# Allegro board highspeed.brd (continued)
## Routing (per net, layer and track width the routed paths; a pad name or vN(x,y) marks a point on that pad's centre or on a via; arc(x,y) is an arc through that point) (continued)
A<0>: length 29.1
  TOP w0.127: U15.47 v1(19.05,91.13)
  BOTTOM w0.127: v1(19.05,91.13) 17.87,89.95 12.14,89.95 10.99,88.81 10.99,72.82 J3.54
A<1>: length 23.9
  TOP w0.127: v1(16.31,87.5) 19.29,87.5 19.68,87.9 U15.46
  BOTTOM w0.127: v1(16.31,87.5) 12.34,87.5 11.32,86.49 11.32,75.04 J3.55
A<2>: length 16.8
  TOP w0.127: U15.44 20.95,87.83 v1(21.11,87.68)
  BOTTOM w0.127: v1(21.11,87.68) 21.11,84.61 J3.56
A<3>: length 22.3
  TOP w0.127: v1(21.46,91.87) 21.46,91.02 21.59,90.89 U15.43
  BOTTOM w0.127: v1(21.46,91.87) 21.46,90.5 16.16,85.2 12.54,85.2 11.65,84.31 11.65,79.79 J3.57
A<4>: length 32.6
  TOP w0.127: v1(22.94,91.87) 22.94,90.97 22.86,90.89 U15.41
  BOTTOM w0.127: J3.58 14.08,79.9 14.08,78.59 13.06,77.58 12.54,77.58 11.65,76.69 11.65,75.66 12.16,75.15 13.34,75.15 21.79,83.6 21.79,89.41 22.94,90.55 v1(22.94,91.87)
A<5>: length 14.8
  TOP w0.127: U15.40 23.5,87.89 22.72,87.11 20.27,87.11 20.27,87.38 v1(20.27,87.38)
  BOTTOM w0.127: v1(20.27,87.38) 20.27,87.38 20.27,86.61 17.48,83.82 J3.59
A<6>: length 14.6
  TOP w0.127: v1(15.65,86.36) 23.97,86.36 24.77,87.15 U15.38
  BOTTOM w0.127: J3.60 v1(15.65,86.36)
A<7>: length 16
  TOP w0.127: J3.61 14,88.9 15.97,86.93 18.19,86.93 18.34,86.78 23.59,86.78 v1(23.95,87.15) ; U15.37 v1(25.4,87.15)
  BOTTOM w0.127: v1(25.4,87.15) 25.4,87.14 23.96,87.14 v1(23.95,87.15)
A<8>: length 31
  TOP w0.127: U14.36 v1(26.04,61.65) ; v1(23.16,49.63) 23.16,49.64 9,49.64 J3.13
  BOTTOM w0.127: v1(23.16,49.63) 26.04,52.5 v1(26.04,61.65)
A<9>: length 31
  TOP w0.127: J3.14 10.63,53.81 10.63,61.07 11.9,62.34 13.54,62.34 v1(15.29,64.08) ; U14.35 v1(26.67,65.1)
  BOTTOM w0.127: v1(26.67,65.1) 25.65,64.08 v1(15.29,64.08)
A<10>: length 31.2
  TOP w0.127: v1(15.67,65.68) 14.97,64.98 12.65,64.98 9.98,62.31 9.98,55.7 J3.15 ; v1(27.81,65.1) 27.81,64.52 27.94,64.39 U14.33
  BOTTOM w0.127: v1(27.81,65.1) 27.23,65.68 v1(15.67,65.68)
A<11>: length 28.3
  TOP w0.127: U14.32 28.57,61.67 27.3,60.4 26.62,60.4 v1(26.62,60.4)
  BOTTOM w0.127: v1(26.62,60.4) 26.62,61.91 25.98,62.54 17.38,62.54 14.46,59.62 14.46,58.63 13.06,57.24 8.98,57.24 J3.16
A<12>: length 31.5
  TOP w0.127: J3.17 9.32,60.12 9.32,64.12 12.25,67.04 15.19,67.04 16.58,65.64 16.58,64.98 v1(16.59,64.97) ; v1(19.02,65.1) 19.59,65.67 29.05,65.67 29.84,64.88 U14.30
  BOTTOM w0.127: v1(19.02,65.1) 18.9,64.97 16.59,64.97 v1(16.59,64.97)
A<13>: length 27.1
  TOP w0.127: v1(21.16,66.27) 29.08,66.27 30.48,64.87 U14.29
  BOTTOM w0.127: v1(21.16,66.27) 14.38,66.27 13.14,65.03 11.69,65.03 J3.18
A<14>: length 28.1
  TOP w0.127: v1(24.36,66.85) 29.84,66.85 31.75,64.95 U14.27
  BOTTOM w0.127: J3.19 8.76,63.5 9.65,64.39 9.65,64.5 12.19,67.04 24.17,67.04 v1(24.36,66.85)
A<15>: length 28.9
  TOP w0.127: J3.20 8.95,67.37 13.82,67.37 v1(14.66,68.2) ; U14.26 32.39,64.95 29.72,67.61 21.49,67.61 v1(21.49,67.61)
  BOTTOM w0.127: v1(21.49,67.61) 21.49,67.62 21.49,68.2 v1(14.66,68.2)
A<16>: length 38.8
  TOP w0.127: v1(16.46,38.68) 16.46,31.7 J3.37 ; U14.47 v1(19.05,61.6)
  BOTTOM w0.127: v1(16.46,38.69) 16.46,60.2 17.86,61.6 v1(19.05,61.6)
A<17>: length 39.6
  TOP w0.127: v1(14.63,37.52) 14.63,37.51 14.63,35.99 13.04,34.4 12.46,34.4 11.32,33.26 11.32,31.86 J3.38 ; U14.46 v1(19.68,60.43)
  BOTTOM w0.127: v1(19.68,60.43) 19.68,60.42 17.75,60.42 17.36,60.03 17.36,38.15 16.72,37.52 v1(14.63,37.52)
A<18>: length 74.1
  TOP w0.127: v1(18.01,59.84) 18.01,59.84 19.94,59.84 20.95,60.86 U14.44 ; J3.39 15.53,35.85 15.53,39.58 v1(18.01,42.06) 31.37,42.06 43.47,54.16 49.72,54.16 U17.6
  BOTTOM w0.127: v1(18.01,59.84) v1(18.01,42.06)
A<19>: length 66.5
  TOP w0.127: 48.89,55.88 48.89,57.66 48.64,57.91 19.26,57.91 v1(18.58,57.23) ; U14.43 v1(21.59,60.43)
  BOTTOM w0.127: v1(21.59,60.43) 20.7,59.54 20.23,59.54 18.58,57.89 v1(18.58,57.23) 18.58,41.37 17.68,40.48 17.68,36.7 16.54,35.56 J3.40
A<20>: length 75.9
  TOP w0.127: J3.41 17.56,42.96 31.74,42.96 43.27,54.49 44.96,54.49 46.36,55.88 ; U14.41 v1(22.86,60.98)
  BOTTOM w0.127: v1(22.86,60.98) 22.85,61 17.79,61 17.03,60.23 17.03,38.35 16.77,38.1 J3.41
A<21>: length 61.1
  TOP w0.127: J3.42 15.81,43.75 17.31,43.75 ; 43.81,55.88 31.36,43.42 17.64,43.42 17.31,43.75 ; U14.40 v1(23.5,61.65) ; v1(19.74,44.09) 17.66,44.09 17.31,43.75
  BOTTOM w0.127: v1(19.74,44.09) 19.74,56.68 23.5,60.44 v1(23.5,61.65)
A<22>: length 60.7
  TOP w0.127: U14.38 v1(24.77,61.65) ; 41.28,55.88 31.93,46.53 v1(15.37,46.53)
  BOTTOM w0.127: v1(24.77,61.65) 24.2,62.22 17.59,62.22 15.31,59.93 15.31,47.16 15.37,47.1 v1(15.37,46.53) 15.37,44.77 13.78,43.18 J3.43
A<23>: length 48.3
  TOP w0.127: J3.44 14.1,47.12 v1(20.95,47.12) 29.97,47.12 U17.1 ; U14.37 v1(25.4,61.06)
  BOTTOM w0.127: v1(20.95,47.12) 20.95,50.12 25.4,54.56 v1(25.4,61.06)
AEN: length 46.9
  TOP w0.127: U17.8 54.16,58.24 18.74,58.24 17.59,57.1 17.59,56.9 14.04,53.34 J3.47
BA<0>: length 133.7
  TOP w0.127: U16.2 v1(19.05,25.93) ; v1(61.29,92.94) 61.29,92.94 61.29,92.33 61.54,92.07 U7.6 ; U15.13 26.04,77.94 27.05,76.93 32.93,76.93 v1(33,76.99) ; U16.13 v1(26.04,26.77)
  BOTTOM w0.127: 26.04,26.15 v1(26.04,26.77) ; 26.04,26.15 25.82,25.93 19.05,25.93 v1(19.05,25.93) ; 26.04,26.15 33.01,26.15 35.55,28.69 35.55,75.71 33.95,77.31 ; v1(61.29,92.94) 61.29,92.94 61.29,93.51 34.74,93.51 33.95,92.71 33.95,77.31 ; 33.95,77.31 33.95,76.99 v1(33,76.99)
BA<1>: length 122.8
  TOP w0.127: v1(66.29,95.2) 66.29,94.21 67.16,93.34 U7.7 ; U16.14 v1(26.67,30.3) ; U16.3 v1(19.68,30.3) ; U15.14 v1(26.67,78.23)
  BOTTOM w0.127: v1(26.67,30.3) 26.67,31.31 26.34,31.64 ; 29,78.56 28.67,78.23 v1(26.67,78.23) ; 29,78.56 29.42,78.13 29.42,64.88 32.14,62.16 32.14,37.94 32.95,37.13 32.95,35.33 31.3,33.68 28.38,33.68 26.34,31.64 ; 29,78.56 29,85.07 30.03,86.1 30.03,90.37 34.86,95.2 v1(66.29,95.2) ; v1(19.68,30.3) 21.02,31.64 26.34,31.64
BA<2>: length 122.4
  TOP w0.127: U15.16 27.94,82.04 28.96,83.06 v1(29.59,83.06) ; U16.5 v1(20.95,30.3) ; U16.16 v1(27.94,30.3) ; U7.8 v1(69.39,94.61)
  BOTTOM w0.127: v1(20.95,30.3) 21.85,29.41 27.04,29.41 v1(27.94,30.3) 30.99,33.35 31.56,33.35 33.59,35.38 33.59,62.91 29.75,66.75 29.75,79.66 29.33,80.08 29.33,82.17 29.59,82.44 v1(29.59,83.06) 30.49,83.95 30.49,90.3 34.8,94.61 v1(69.39,94.61)
BA<3>: length 129.2
  TOP w0.127: v1(21.59,26.85) U16.6 21.59,30.68 22.38,31.47 31.75,31.47 v1(31.75,31.47) ; v1(30.48,82.47) 29.46,82.47 28.57,81.58 U15.17 ; U16.17 v1(28.57,26.85) ; U7.9 66.14,95.88 65.51,95.25 65.51,93.83 v1(65.51,93.83)
  BOTTOM w0.127: v1(21.59,26.85) 22.08,27.34 28.08,27.34 v1(28.57,26.85) ; v1(65.51,93.83) 65.5,93.83 34.61,93.83 31.68,90.91 31.68,83.68 v1(30.48,82.47) 30.48,70.76 34.24,66.99 34.24,33.7 32.34,31.8 31.76,31.8 31.76,31.48 v1(31.75,31.47)
BA<4>: length 75.3
  TOP w0.127: U16.19 v1(29.84,26.85) ; U15.19 29.84,81.69 v1(29.9,81.74) ; U16.8 v1(22.86,26.77)
  BOTTOM w0.127: v1(29.9,81.74) 30.08,81.55 30.08,69.85 33.92,66.01 33.92,34.6 29.84,30.53 29.84,27.67 ; 29.84,27.67 v1(29.84,26.85) ; 29.84,27.67 21.53,27.67 21.02,27.16 21.02,26.53 21.27,26.28 22.37,26.28 v1(22.86,26.77)
BA<5>: length 73.2
  TOP w0.127: U15.20 30.48,77.49 v1(31.06,77.49) ; v1(33.73,30.89) 33.73,27.25 32.33,25.85 24.64,25.85 23.5,26.99 U16.9 ; U16.20 v1(30.48,30.3)
  BOTTOM w0.127: v1(31.06,77.49) 31.06,71.58 34.57,68.08 34.57,31.72 v1(33.73,30.89) 31.06,30.89 v1(30.48,30.3)
BA<6>: length 67.3
  TOP w0.127: v1(31.75,30.3) U16.22 31.75,26.57 31.35,26.18 25.65,26.18 24.77,27.07 U16.11 ; U15.22 v1(31.75,78.28)
  BOTTOM w0.127: v1(31.75,30.3) 32.65,29.41 33.37,29.41 34.9,30.93 34.9,69.2 31.75,72.34 v1(31.75,78.28)
BA<7>: length 71.8
  TOP w0.127: U15.23 v1(32.39,81.74) ; U16.12 25.4,30.08 26.19,30.87 31.99,30.87 32.39,30.47 U16.23 v1(32.39,26.72)
  BOTTOM w0.127: v1(32.39,26.72) 35.22,29.56 35.22,70.18 32.39,73.02 v1(32.39,81.74)
BD<0>: length 44.4
  TOP w0.127: U15.12 25.4,81.81 26.04,82.45 v1(26.7,82.45) ; v1(51.9,96.88) 51.37,97.41 51.37,97.45 51.17,97.65 51.17,97.89 51.04,98.03 50.75,98.03 49.53,99.25 U7.25
  BOTTOM w0.127: v1(51.9,96.88) 51.77,96.75 31.95,96.75 26.7,91.49 v1(26.7,82.45)
BD<1>: length 56.3
  TOP w0.127: U7.24 50.8,98.73 51.5,98.03 51.5,97.78 51.83,97.45 52.14,97.45 52.47,97.12 52.47,96.64 52.14,96.31 51.66,96.31 51.33,96.64 51.33,96.99 50.86,97.46 v1(50,97.46) ; v1(33.58,97.46) 33.59,97.45 33.59,76.74 33.19,76.34 26.92,76.34 24.77,78.5 U15.11
  BOTTOM w0.127: v1(50,97.46) v1(33.58,97.46)
BD<2>: length 43.6
  TOP w0.127: U15.9 23.5,81.8 24.26,82.56 v1(24.26,83.24) ; U7.23 v1(52.07,98.02)
  BOTTOM w0.127: v1(24.26,83.24) 26.35,85.33 26.35,91.99 32.39,98.03 52.06,98.03 v1(52.07,98.02)
BD<3>: length 49.6
  TOP w0.127: U15.8 v1(22.86,77.57) ; U7.22 v1(53.34,95.78)
  BOTTOM w0.127: v1(22.86,77.57) 24.09,78.8 25.18,78.8 28.48,82.1 28.48,90.01 34.25,95.78 v1(53.34,95.78)
BD<4>: length 52.2
  TOP w0.127: U15.6 v1(21.59,82.09) ; U7.21 v1(54.61,102.64)
  BOTTOM w0.127: v1(21.59,82.09) 22.12,82.62 22.12,88.14 23.83,89.86 23.83,91.95 24.65,92.77 24.65,95.67 31.63,102.65 54.6,102.65 v1(54.61,102.64)
BD<5>: length 49.5
  TOP w0.127: U7.20 v1(55.88,98.58) ; U15.5 20.95,82.32 21.84,83.21 23.19,83.21 v1(23.19,83.21)
  BOTTOM w0.127: v1(55.88,98.58) 55.87,98.59 31.98,98.59 27.41,94.02 27.41,93.73 25.97,92.29 25.97,85.99 v1(23.19,83.21)
BD<6>: length 52.1
  TOP w0.127: U7.19 v1(57.15,97.18) ; v1(27.58,83.8) 27.57,83.8 21.97,83.8 19.68,81.52 U15.3
  BOTTOM w0.127: v1(57.15,97.18) 57.14,97.19 53.02,97.19 52.14,96.31 51.65,96.31 51.52,96.18 33.93,96.18 27.58,89.84 v1(27.58,83.8)
BD<7>: length 68.2
  TOP w0.127: v1(34.75,92.69) 34.75,76.86 30.68,72.8 24.77,72.8 19.05,78.51 U15.2 ; U7.18 v1(58.42,92.94)
  BOTTOM w0.127: v1(58.42,92.94) 58.17,92.68 v1(34.75,92.68)
BD<8>: length 3.6
  TOP w0.127: U14.13 26.04,55.46 25.4,55.46 U14.12
BD<9>: length 4.9
  TOP w0.127: U14.14 26.67,52.49 24.77,52.49 U14.11
BD<10>: length 8.7
  TOP w0.127: U14.9 23.5,55.79 24.13,56.42 27.54,56.42 27.94,56.03 U14.16
BD<11>: length 9
  TOP w0.127: U14.17 28.57,52.42 28.32,52.16 23.11,52.16 22.86,52.42 U14.8
BD<12>: length 12.3
  TOP w0.127: U14.6 21.59,55.48 22.86,56.75 28.57,56.75 29.84,55.48 U14.19
BD<13>: length 13.9
  TOP w0.127: U14.5 20.95,55.55 22.48,57.08 28.96,57.08 30.48,55.55 U14.20
BD<14>: length 15.7
  TOP w0.127: U14.3 19.68,52.47 20.48,51.68 30.96,51.68 31.75,52.47 U14.22
BD<15>: length 17.4
  TOP w0.127: U14.23 32.39,52.37 31.37,51.35 20.07,51.35 19.05,52.37 U14.2
BNC2: length 20.1
  TOP w0.2: L1.2 127.71,24.77 C9.1
  TOP w1.5: J1.1 125.3,32.38 122.56,29.63 L1.2
BNC3: length 22.4
  TOP w0.2: C13.1 121.83,4.28
  TOP w0.5: 121.83,4.28 L4.2
  TOP w1.5: J2.1 124.1,11.68 121.79,9.37 L4.2
BR<0>: length 55.4
  TOP w0.127: U25.19 222.47,22.52 227.91,27.97 233.41,27.97 238.11,32.67 242.4,36.96 252.48,36.96
BR<1>: length 54.9
  TOP w0.127: U25.18 222.99,21.25 228.44,26.7 233.94,26.7 239.01,31.77 241.65,34.42 252.48,34.42
BR<2>: length 54.4
  TOP w0.127: J5.59 240.91,31.88 239.91,30.87 234.46,25.43 228.96,25.43 223.52,19.98 U25.17
BR<3>: length 53.9
  TOP w0.127: 252.48,29.34 252.22,29.08 239.91,29.08 234.99,24.16 229.49,24.16 224.05,18.71 U25.16
BR<4>: length 53.6
  TOP w0.127: U25.15 224.57,17.45 230.02,22.89 235.52,22.89 239.61,26.98 251.79,26.98 251.91,27.11 252.17,27.11 J5.61
BR<5>: length 54.1
  TOP w0.127: 252.48,24.26 250.95,25.78 240.2,25.78 236.05,21.62 230.55,21.62 225.1,16.18 203.01,16.18
BR<6>: length 53.8
  TOP w0.127: 252.48,21.72 250.4,21.72 248.54,23.58 239.8,23.58 236.57,20.35 231.07,20.35 225.63,14.91 U25.13
BR<7>: length 52.6
  TOP w0.127: 203.01,13.64 226.16,13.64 231.6,19.08 237.1,19.08 238.2,20.18 251.47,20.18 252.48,19.18
BRD: length 13
  TOP w0.127: U7.73 v1(64.77,69.49)
  BOTTOM w0.127: v1(64.77,69.49) 64.61,69.66 60.07,69.66 59.05,68.64 U17.16
BRESET: length 39.6
  TOP w0.127: U7.12 66.04,99.54 63.36,96.87 63.3,96.87 60.38,93.94 v1(60.38,69.09)
  BOTTOM w0.127: v1(60.38,69.09) 60.38,64.72 61.59,63.5
BWR: length 26.2
  TOP w0.127: U17.17 54.44,65.57 39.01,65.57 37.61,66.97 37.61,68.09 38.88,69.36 39.52,69.36 40.64,70.48 U7.54
CLK1_N: length 279.3
  TOP w0.2: U8.19 151.22,56.53 151.65,56.96 157.77,56.96 158.21,57.39 158.21,60.4 158.41,60.6 159.01,60.6 159.21,60.4 159.21,53.76 159.64,53.32 160.57,53.32 161.01,53.76 161.01,60.4 161.21,60.6 161.81,60.6 162.01,60.4 162.01,57.39 162.44,56.96 164.16,56.96 166.99,54.13 166.99,51.77 173.45,45.31 174.06,45.31 175.76,47.01 176.04,47.01 176.47,46.59 176.47,46.3 172.62,42.46 172.62,41.85 173.28,41.19 173.9,41.19 177.74,45.03 178.02,45.03 178.45,44.61 178.45,44.32 174.6,40.48 174.6,39.87 175.27,39.2 175.88,39.2 177.58,40.9 177.86,40.9 178.99,39.77 199.09,39.77 199.53,40.2 199.53,42.92 199.73,43.12 200.33,43.12 200.53,42.92 200.53,40.2 200.96,39.77 201.89,39.77 202.33,40.2 202.33,42.92 202.53,43.12 203.13,43.12 203.33,42.92 203.33,40.2 203.76,39.77 204.69,39.77 205.13,40.2 205.13,42.92 205.33,43.12 205.93,43.12 206.13,42.92 206.13,40.2 206.56,39.77 207.49,39.77 207.93,40.2 207.93,42.92 208.13,43.12 208.73,43.12 208.93,42.92 208.93,40.2 209.36,39.77 210.29,39.77 210.73,40.2 210.73,42.92 210.93,43.12 211.53,43.12 211.73,42.92 211.73,40.2 212.16,39.77 213.09,39.77 213.53,40.2 213.53,42.92 213.73,43.12 214.33,43.12 214.53,42.92 214.53,40.2 214.96,39.77 215.89,39.77 216.33,40.2 216.33,42.92 216.53,43.12 217.13,43.12 217.33,42.92 217.33,40.2 217.76,39.77 225.99,39.77 229.01,42.79 229.01,44.56 229.35,44.9 v1(229.35,45.43) ; J5.2 256.52,96.41 238.44,96.41 229.01,86.99 229.01,83.12 v1(229.35,82.78)
  BOTTOM w0.2: v1(229.35,82.78) 229.35,82.25 229.01,81.91 229.01,64.79 228.58,64.36 227.64,64.36 227.21,64.79 227.21,66.5 227.01,66.7 226.41,66.7 226.21,66.5 226.21,64.79 225.78,64.36 224.84,64.36 224.41,64.79 224.41,66.5 224.21,66.7 223.61,66.7 223.41,66.5 223.41,64.79 222.98,64.36 222.04,64.36 221.61,64.79 221.61,66.5 221.41,66.7 220.81,66.7 220.61,66.5 220.61,63.55 220.81,63.36 228.58,63.36 229.01,62.92 229.01,46.3 229.35,45.96 v1(229.35,45.43)
CLK1_P: length 279.3
  TOP w0.2: J5.1 256.45,96.81 238.27,96.81 228.6,87.15 228.6,83.11 v1(228.27,82.78) ; U8.20 151.22,57.8 151.65,57.36 157.61,57.36 157.81,57.56 157.81,60.56 158.24,61 159.17,61 159.61,60.56 159.61,53.92 159.81,53.72 160.41,53.72 160.61,53.92 160.61,60.56 161.04,61 161.97,61 162.41,60.56 162.41,57.56 162.61,57.36 164.33,57.36 167.39,54.3 167.39,51.94 173.62,45.71 173.9,45.71 175.59,47.41 176.21,47.41 176.87,46.75 176.87,46.14 173.02,42.29 173.02,42.01 173.45,41.59 173.73,41.59 177.58,45.43 178.19,45.43 178.85,44.77 178.85,44.16 175,40.31 175,40.03 175.43,39.6 175.71,39.6 177.41,41.3 178.02,41.3 179.16,40.17 198.93,40.17 199.13,40.37 199.13,43.08 199.56,43.52 200.49,43.52 200.93,43.08 200.93,40.37 201.13,40.17 201.73,40.17 201.93,40.37 201.93,43.08 202.36,43.52 203.29,43.52 203.73,43.08 203.73,40.37 203.93,40.17 204.53,40.17 204.73,40.37 204.73,43.08 205.16,43.52 206.09,43.52 206.53,43.08 206.53,40.37 206.73,40.17 207.33,40.17 207.53,40.37 207.53,43.08 207.96,43.52 208.89,43.52 209.33,43.08 209.33,40.37 209.53,40.17 210.13,40.17 210.33,40.37 210.33,43.08 210.76,43.52 211.69,43.52 212.13,43.08 212.13,40.37 212.33,40.17 212.93,40.17 213.13,40.37 213.13,43.08 213.56,43.52 214.49,43.52 214.93,43.08 214.93,40.37 215.13,40.17 215.73,40.17 215.93,40.37 215.93,43.08 216.36,43.52 217.29,43.52 217.73,43.08 217.73,40.37 217.93,40.17 225.82,40.17 228.61,42.96 228.61,44.56 228.27,44.9 v1(228.27,45.43)
  BOTTOM w0.2: v1(228.27,45.43) 228.27,45.96 228.61,46.3 228.61,62.76 228.41,62.96 220.64,62.96 220.21,63.39 220.21,66.66 220.64,67.1 221.58,67.1 222.01,66.66 222.01,64.95 222.21,64.75 222.81,64.75 223.01,64.95 223.01,66.66 223.44,67.1 224.38,67.1 224.81,66.66 224.81,64.95 225.01,64.75 225.61,64.75 225.81,64.95 225.81,66.66 226.24,67.1 227.18,67.1 227.61,66.66 227.61,64.95 227.81,64.75 228.41,64.75 228.61,64.95 228.61,81.91 228.27,82.25 v1(228.27,82.78)
CLK2_N: length 282.5
  TOP w0.2: J5.4 256.57,91.28 253.13,91.28 253.07,91.33 238.66,91.33 232.02,84.7 232.02,83.64 232,83.62 232,83.25 232.34,82.91 v1(232.34,82.38) ; v1(233.44,46.19) 233.44,45.66 233.1,45.32 233.1,43.68 226.65,37.23 213.52,37.23 213.32,37.03 213.32,36.02 212.88,35.59 211.95,35.59 211.52,36.02 211.52,38.67 211.32,38.87 210.72,38.87 210.52,38.67 210.52,36.02 210.08,35.59 209.15,35.59 208.72,36.02 208.72,38.67 208.52,38.87 207.92,38.87 207.72,38.67 207.72,36.02 207.28,35.59 206.35,35.59 205.92,36.02 205.92,38.67 205.72,38.87 205.12,38.87 204.92,38.67 204.92,36.02 204.48,35.59 203.55,35.59 203.12,36.02 203.12,38.67 202.92,38.87 202.32,38.87 202.12,38.67 202.12,36.02 201.68,35.59 200.75,35.59 200.32,36.02 200.32,38.67 200.12,38.87 199.52,38.87 199.32,38.67 199.32,36.02 198.88,35.59 197.95,35.59 197.52,36.02 197.52,38.67 197.32,38.87 196.72,38.87 196.52,38.67 196.52,36.02 196.08,35.59 195.15,35.59 194.72,36.02 194.72,38.67 194.52,38.87 193.92,38.87 193.72,38.67 193.72,36.02 193.28,35.59 192.35,35.59 191.92,36.02 191.92,38.67 191.72,38.87 191.12,38.87 190.92,38.67 190.92,36.02 190.48,35.59 189.55,35.59 189.12,36.02 189.12,38.67 188.92,38.87 188.32,38.87 188.12,38.67 188.12,36.02 187.68,35.59 186.75,35.59 186.32,36.02 186.32,38.67 186.12,38.87 185.52,38.87 185.32,38.67 185.32,36.02 184.88,35.59 183.95,35.59 183.52,36.02 183.52,38.67 183.32,38.87 182.72,38.87 182.52,38.67 182.52,36.02 182.08,35.59 181.15,35.59 180.72,36.02 180.72,37.03 180.52,37.23 171.49,37.23 169.27,39.45 168.99,39.45 167.44,37.91 166.83,37.91 166.17,38.57 166.17,39.18 169.7,42.71 169.7,42.99 169.28,43.42 168.99,43.42 165.46,39.89 164.85,39.89 164.19,40.55 164.19,41.16 167.72,44.69 167.72,44.98 167.3,45.4 167.01,45.4 163.48,41.87 162.87,41.87 162.21,42.53 162.21,43.14 165.74,46.67 165.74,46.96 165.31,47.38 165.03,47.38 161.5,43.85 160.89,43.85 160.23,44.51 160.23,45.12 163.76,48.66 163.76,48.94 163.33,49.36 163.05,49.36 159.52,45.83 158.91,45.83 158.25,46.49 158.25,47.11 161.78,50.64 161.78,50.92 161.35,51.34 161.07,51.34 159.53,49.8 158.92,49.8 158.22,50.5 154.3,54.42 151.65,54.42 151.22,53.98 U8.17
  BOTTOM w0.2: v1(232.34,82.38) 232.34,81.85 232,81.51 232,48.86 233.1,47.76 233.1,47.06 233.44,46.72 v1(233.44,46.19)
CLK2_P: length 282.7
  TOP w0.2: U8.18 151.22,55.26 151.65,54.82 154.46,54.82 158.38,50.9 158.38,50.9 159.08,50.2 159.36,50.2 160.91,51.74 161.52,51.74 162.18,51.08 162.18,50.47 158.65,46.94 158.65,46.66 159.07,46.23 159.35,46.23 162.89,49.76 163.5,49.76 164.16,49.1 164.16,48.49 160.63,44.96 160.63,44.68 161.06,44.25 161.34,44.25 164.87,47.78 165.48,47.78 166.14,47.12 166.14,46.51 162.61,42.98 162.61,42.7 163.04,42.27 163.32,42.27 166.85,45.8 167.46,45.8 168.12,45.14 168.12,44.53 164.59,41 164.59,40.72 165.02,40.29 165.3,40.29 168.83,43.82 169.44,43.82 170.1,43.16 170.1,42.55 166.57,39.02 166.57,38.73 167,38.31 167.28,38.31 168.82,39.85 169.44,39.85 171.66,37.63 180.68,37.63 181.12,37.2 181.12,36.19 181.32,35.99 181.92,35.99 182.12,36.19 182.12,38.84 182.55,39.27 183.48,39.27 183.92,38.84 183.92,36.19 184.12,35.99 184.72,35.99 184.92,36.19 184.92,38.84 185.35,39.27 186.28,39.27 186.72,38.84 186.72,36.19 186.92,35.99 187.52,35.99 187.72,36.19 187.72,38.84 188.15,39.27 189.08,39.27 189.52,38.84 189.52,36.19 189.72,35.99 190.32,35.99 190.52,36.19 190.52,38.84 190.95,39.27 191.88,39.27 192.32,38.84 192.32,36.19 192.52,35.99 193.12,35.99 193.32,36.19 193.32,38.84 193.75,39.27 194.68,39.27 195.12,38.84 195.12,36.19 195.32,35.99 195.92,35.99 196.12,36.19 196.12,38.84 196.55,39.27 197.48,39.27 197.92,38.84 197.92,36.19 198.12,35.99 198.72,35.99 198.92,36.19 198.92,38.84 199.35,39.27 200.28,39.27 200.72,38.84 200.72,36.19 200.92,35.99 201.52,35.99 201.72,36.19 201.72,38.84 202.15,39.27 203.08,39.27 203.52,38.84 203.52,36.19 203.72,35.99 204.32,35.99 204.52,36.19 204.52,38.84 204.95,39.27 205.88,39.27 206.32,38.84 206.32,36.19 206.52,35.99 207.12,35.99 207.32,36.19 207.32,38.84 207.75,39.27 208.68,39.27 209.12,38.84 209.12,36.19 209.32,35.99 209.92,35.99 210.12,36.19 210.12,38.84 210.55,39.27 211.48,39.27 211.92,38.84 211.92,36.19 212.12,35.99 212.72,35.99 212.92,36.19 212.92,37.2 213.35,37.63 226.48,37.63 232.7,43.85 232.7,45.32 232.36,45.66 v1(232.36,46.19) ; v1(231.26,82.38) 231.26,82.91 231.6,83.25 231.6,83.79 231.62,83.81 231.62,84.86 238.49,91.73 253.07,91.73 253.13,91.68 256.5,91.68 257.56,92.74 257.56,92.84
  BOTTOM w0.2: v1(232.36,46.19) 232.36,46.72 232.7,47.06 232.7,47.6 231.6,48.7 231.6,81.51 231.26,81.85 v1(231.26,82.38)
CLK3_N: length 276.4
  TOP w0.2: v1(237.54,43.78) 237.54,43.25 237.2,42.91 237.2,42.21 235.46,40.46 233.58,40.46 226.54,33.42 166.39,33.42 163.95,35.87 163.95,36.48 164.5,37.03 164.5,37.31 164.07,37.74 163.79,37.74 162.24,36.19 161.63,36.19 160.97,36.85 160.97,37.47 162.51,39.01 162.51,39.29 162.09,39.72 161.81,39.72 160.26,38.17 159.65,38.17 158.99,38.83 158.99,39.45 160.53,40.99 160.53,41.27 160.11,41.7 159.83,41.7 158.28,40.15 157.67,40.15 157.01,40.82 157.01,41.43 158.55,42.97 158.55,43.25 158.13,43.68 157.84,43.68 157.3,43.13 156.68,43.13 154.39,45.42 154.39,48.92 152.71,50.61 151.65,50.61 151.22,50.18 U8.14 ; v1(235.84,78.28) 235.84,78.81 235.5,79.15 235.5,82.38 239.38,86.25 242.03,86.25 242.47,86.69 242.47,89.13 242.67,89.33 243.27,89.33 243.47,89.13 243.47,83.62 243.9,83.18 244.83,83.18 245.27,83.62 245.27,89.13 245.47,89.33 246.07,89.33 246.27,89.13 246.27,83.62 246.7,83.18 247.63,83.18 248.07,83.62 248.07,89.13 248.27,89.33 248.87,89.33 249.07,89.13 249.07,86.69 249.5,86.25 256.52,86.25 J5.6
  BOTTOM w0.2: v1(235.84,78.28) 235.84,77.75 235.5,77.41 235.5,77.04 236.5,76.04 236.5,73.82 236.7,73.62 239,73.62 239.44,73.18 239.44,72.25 239,71.82 233.76,71.82 233.56,71.62 233.56,71.02 233.76,70.82 239,70.82 239.44,70.38 239.44,69.45 239,69.02 233.76,69.02 233.56,68.82 233.56,68.22 233.76,68.02 239,68.02 239.44,67.58 239.44,66.65 239,66.22 233.76,66.22 233.56,66.02 233.56,65.42 233.76,65.22 236.07,65.22 236.5,64.78 236.5,61.46 236.7,61.26 238.31,61.26 238.75,60.83 238.75,59.9 238.31,59.46 234.45,59.46 234.25,59.26 234.25,58.66 234.45,58.46 238.31,58.46 238.75,58.03 238.75,57.1 238.31,56.66 234.45,56.66 234.25,56.46 234.25,55.86 234.45,55.66 238.31,55.66 238.75,55.23 238.75,54.3 238.31,53.86 234.45,53.86 234.25,53.66 234.25,53.06 234.45,52.86 238.31,52.86 238.75,52.43 238.75,51.5 238.31,51.06 234.45,51.06 234.25,50.86 234.25,50.26 234.45,50.06 236.07,50.06 236.5,49.63 236.5,45.59 236.77,45.59 237.2,45.16 237.2,44.65 237.54,44.31 v1(237.54,43.78)
CLK3_P: length 276.4
  TOP w0.2: U8.15 151.22,51.45 151.65,51.01 152.87,51.01 154.79,49.09 154.79,45.59 156.85,43.53 157.13,43.53 157.68,44.08 158.29,44.08 158.95,43.42 158.95,42.81 157.41,41.26 157.41,40.98 157.83,40.55 158.11,40.55 159.66,42.1 160.27,42.1 160.93,41.44 160.93,40.83 159.39,39.28 159.39,39 159.82,38.57 160.1,38.57 161.64,40.12 162.25,40.12 162.91,39.46 162.91,38.84 161.37,37.3 161.37,37.02 161.8,36.59 162.08,36.59 163.62,38.14 164.24,38.14 164.9,37.48 164.9,36.86 164.35,36.31 164.35,36.03 166.56,33.82 226.37,33.82 233.42,40.86 235.29,40.86 236.8,42.37 236.8,42.91 236.46,43.25 v1(236.46,43.78) ; 257.56,87.76 256.45,86.66 249.67,86.66 249.47,86.85 249.47,89.29 249.03,89.73 248.1,89.73 247.67,89.29 247.67,83.78 247.47,83.58 246.87,83.58 246.67,83.78 246.67,89.29 246.23,89.73 245.3,89.73 244.87,89.29 244.87,83.78 244.67,83.58 244.07,83.58 243.87,83.78 243.87,89.29 243.44,89.73 242.5,89.73 242.07,89.29 242.07,86.85 241.87,86.66 239.21,86.66 235.1,82.55 235.1,79.15 234.76,78.81 v1(234.76,78.28)
  BOTTOM w0.2: v1(236.46,43.78) 236.46,44.31 236.8,44.65 236.8,44.99 236.6,45.19 236.3,45.19 236.1,45.39 236.1,49.46 235.9,49.66 234.28,49.66 233.85,50.1 233.85,51.03 234.28,51.46 238.15,51.46 238.35,51.66 238.35,52.26 238.15,52.46 234.28,52.46 233.85,52.9 233.85,53.83 234.28,54.26 238.15,54.26 238.35,54.46 238.35,55.06 238.15,55.26 234.28,55.26 233.85,55.7 233.85,56.63 234.28,57.06 238.15,57.06 238.35,57.26 238.35,57.86 238.15,58.06 234.28,58.06 233.85,58.5 233.85,59.43 234.28,59.86 238.15,59.86 238.35,60.06 238.35,60.66 238.15,60.86 236.53,60.86 236.1,61.3 236.1,64.62 235.9,64.82 233.6,64.82 233.16,65.25 233.16,66.18 233.6,66.62 238.84,66.62 239.04,66.82 239.04,67.42 238.84,67.62 233.6,67.62 233.16,68.05 233.16,68.98 233.6,69.42 238.84,69.42 239.04,69.62 239.04,70.22 238.84,70.42 233.6,70.42 233.16,70.85 233.16,71.78 233.6,72.22 238.84,72.22 239.04,72.42 239.04,73.02 238.84,73.22 236.53,73.22 236.1,73.65 236.1,75.87 235.1,76.87 235.1,77.41 234.76,77.75 v1(234.76,78.28)
CLK4_N: length 285.8
  TOP w0.2: v1(240.94,75.08) 240.94,75.61 240.6,75.95 240.6,80.01 241.77,81.19 256.5,81.19 J5.8 ; v1(239.19,42.03) 239.15,42.03 237.9,40.78 237.9,40.48 228.3,30.88 223.74,30.88 223.54,30.68 223.54,27.14 223.11,26.71 222.18,26.71 221.74,27.14 221.74,30.68 221.54,30.88 220.94,30.88 220.74,30.68 220.74,27.14 220.31,26.71 219.38,26.71 218.94,27.14 218.94,30.68 218.74,30.88 218.14,30.88 217.94,30.68 217.94,27.14 217.51,26.71 216.58,26.71 216.14,27.14 216.14,30.68 215.94,30.88 215.34,30.88 215.14,30.68 215.14,27.14 214.71,26.71 213.78,26.71 213.34,27.14 213.34,30.68 213.14,30.88 212.54,30.88 212.34,30.68 212.34,27.14 211.91,26.71 210.98,26.71 210.54,27.14 210.54,30.68 210.34,30.88 209.74,30.88 209.54,30.68 209.54,27.14 209.11,26.71 208.18,26.71 207.74,27.14 207.74,30.68 207.54,30.88 206.94,30.88 206.74,30.68 206.74,27.14 206.31,26.71 205.38,26.71 204.94,27.14 204.94,30.68 204.74,30.88 204.14,30.88 203.94,30.68 203.94,27.14 203.51,26.71 202.58,26.71 202.14,27.14 202.14,30.68 201.94,30.88 201.34,30.88 201.14,30.68 201.14,27.14 200.71,26.71 199.78,26.71 199.34,27.14 199.34,30.68 199.14,30.88 198.54,30.88 198.34,30.68 198.34,27.14 197.91,26.71 196.98,26.71 196.54,27.14 196.54,30.68 196.34,30.88 161,30.88 156.96,34.92 156.68,34.92 155.86,34.1 155.25,34.1 154.66,34.69 154.66,35.3 156.75,37.39 156.75,37.67 156.39,38.03 156.11,38.03 154.02,35.94 153.41,35.94 152.82,36.53 152.82,37.14 154.91,39.23 154.91,39.51 154.55,39.87 154.27,39.87 153.45,39.05 152.83,39.05 151.85,40.03 151.85,47.87 151.65,48.07 151.22,47.64 150.01,47.64
  BOTTOM w0.2: v1(240.94,75.08) 240.94,74.55 240.6,74.21 240.6,63.92 240.8,63.72 241.4,63.72 241.6,63.92 241.6,66.66 242.03,67.1 242.97,67.1 243.4,66.66 243.4,63.92 243.6,63.72 244.2,63.72 244.4,63.92 244.4,66.66 244.83,67.1 245.77,67.1 246.2,66.66 246.2,63.92 246.4,63.72 247,63.72 247.2,63.92 247.2,66.66 247.63,67.1 248.57,67.1 249,66.66 249,62.35 248.57,61.92 240.8,61.92 240.6,61.72 240.6,46.08 239.14,44.62 239.14,43.53 238.85,43.24 238.85,42.9 239.19,42.56 v1(239.19,42.03)
CLK4_P: length 285.5
  TOP w0.2: v1(239.86,75.08) 239.86,75.61 240.2,75.95 240.2,80.18 241.61,81.59 256.47,81.59 257.56,82.68 ; v1(238.11,42.03) 238.11,41.56 237.5,40.95 237.5,40.65 228.13,31.28 223.58,31.28 223.14,30.85 223.14,27.31 222.94,27.11 222.34,27.11 222.14,27.31 222.14,30.85 221.71,31.28 220.78,31.28 220.34,30.85 220.34,27.31 220.14,27.11 219.54,27.11 219.34,27.31 219.34,30.85 218.91,31.28 217.98,31.28 217.54,30.85 217.54,27.31 217.34,27.11 216.74,27.11 216.54,27.31 216.54,30.85 216.11,31.28 215.18,31.28 214.74,30.85 214.74,27.31 214.54,27.11 213.94,27.11 213.74,27.31 213.74,30.85 213.31,31.28 212.38,31.28 211.94,30.85 211.94,27.31 211.74,27.11 211.14,27.11 210.94,27.31 210.94,30.85 210.51,31.28 209.58,31.28 209.14,30.85 209.14,27.31 208.94,27.11 208.34,27.11 208.14,27.31 208.14,30.85 207.71,31.28 206.78,31.28 206.34,30.85 206.34,27.31 206.14,27.11 205.54,27.11 205.34,27.31 205.34,30.85 204.91,31.28 203.98,31.28 203.54,30.85 203.54,27.31 203.34,27.11 202.74,27.11 202.54,27.31 202.54,30.85 202.11,31.28 201.18,31.28 200.74,30.85 200.74,27.31 200.54,27.11 199.94,27.11 199.74,27.31 199.74,30.85 199.31,31.28 198.38,31.28 197.94,30.85 197.94,27.31 197.74,27.11 197.14,27.11 196.94,27.31 196.94,30.85 196.51,31.28 161.17,31.28 157.13,35.32 156.52,35.32 155.7,34.5 155.41,34.5 155.06,34.85 155.06,35.14 157.15,37.22 157.15,37.83 156.55,38.43 155.94,38.43 153.86,36.34 153.57,36.34 153.22,36.69 153.22,36.98 155.31,39.06 155.31,39.67 154.71,40.27 154.1,40.27 153.28,39.45 153,39.45 152.25,40.19 152.25,48.04 151.82,48.47 151.65,48.47 151.22,48.91 U8.13
  BOTTOM w0.2: v1(238.11,42.03) 238.11,42.56 238.45,42.9 238.45,43.41 238.74,43.69 238.74,44.78 240.2,46.25 240.2,61.89 240.63,62.32 248.4,62.32 248.6,62.52 248.6,66.5 248.4,66.7 247.8,66.7 247.6,66.5 247.6,63.75 247.17,63.32 246.23,63.32 245.8,63.75 245.8,66.5 245.6,66.7 245,66.7 244.8,66.5 244.8,63.75 244.37,63.32 243.43,63.32 243,63.75 243,66.5 242.8,66.7 242.2,66.7 242,66.5 242,63.75 241.57,63.32 240.63,63.32 240.2,63.75 240.2,74.21 239.86,74.55 v1(239.86,75.08)
CLOCK_IO: length 330.9
  TOP w0.127: 125.3,51.38 133.25,51.38 arc(133.65,51.22) 133.81,50.82 133.81,40.44 134.14,40.11 136.02,40.11 arc(136.58,40.67) 136.02,41.24 135.5,41.24 arc(134.94,41.8) 135.5,42.36 136.02,42.36 arc(136.58,42.93) 136.02,43.49 135.5,43.49 arc(134.94,44.05) 135.5,44.62 136.02,44.62 arc(136.58,45.18) 136.02,45.75 135.5,45.75 arc(134.94,46.31) 135.5,46.87 136.02,46.87 arc(136.58,47.44) 136.02,48 135.5,48 arc(134.94,48.56) 135.5,49.13 136.02,49.13 arc(136.58,49.69) 136.02,50.25 135.5,50.25 arc(134.94,50.82) 135.5,51.38 136.02,51.38 arc(136.58,51.94) 136.02,52.51 135.5,52.51 arc(134.94,53.07) 135.5,53.63 136.02,53.63 arc(136.58,54.2) 136.02,54.76 135.5,54.76 arc(134.94,55.33) 135.5,55.89 136.02,55.89 arc(136.58,56.45) 136.02,57.02 135.5,57.02 arc(134.94,57.58) 135.5,58.14 136.02,58.14 arc(136.58,58.71) 136.02,59.27 135.5,59.27 arc(134.94,59.83) 135.5,60.4 136.02,60.4 arc(136.58,60.96) 136.02,61.52 135.5,61.52 arc(134.94,62.09) 135.5,62.65 arc(135.8,62.77) 135.92,63.06 135.92,69.77 arc(136.33,70.18) 136.74,69.77 136.74,62.88 arc(136.81,62.72) 136.97,62.65 arc(137.13,62.58) 137.2,62.42 137.2,51.79 arc(137.32,51.5) 137.61,51.38 138.47,51.38 138.6,51.51 138.6,56.05 138.73,56.18 140.47,56.18 U8.2 ; 125.3,51.38 125.3,71.45 125.43,71.58 127.65,71.58 arc(127.94,71.46) 128.06,71.17 128.06,61.39 arc(128.47,60.98) 128.89,61.39 128.89,71.17 arc(129.3,71.58) 129.71,71.17 129.71,61.39 arc(130.13,60.98) 130.54,61.39 130.54,71.17 arc(130.96,71.58) 131.37,71.17 131.37,61.39 arc(131.78,60.98) 132.2,61.39 132.2,71.17 arc(132.32,71.46) 132.61,71.58 142.61,71.58 U24.11 ; 125.3,51.38 125.3,44.89 126.61,43.58 v1(131.2,43.58) ; v1(189.2,8.28) 198.92,8.28 U25.11
  TOP w0.802: R19.2 125.3,51.38
  BOTTOM w0.127: v1(189.2,8.28) 182.9,14.58 176.5,14.58 148.6,42.48 138.7,42.48 137.6,43.58 v1(131.2,43.58)
D<0>: length 92.4
  TOP w0.127: U16.26 v1(32.39,35.66) ; U16.37 v1(25.4,35.66) v1(25.4,34.37)
  BOTTOM w0.127: J3.28 4.61,83.35 4.61,31.97 7.15,29.43 15.91,29.43 18.78,32.3 23.33,32.3 v1(25.4,34.37) ; v1(25.4,35.66) v1(32.39,35.66)
D<1>: length 73.1
  TOP w0.127: v1(14.58,45.85) 23.14,45.85 v1(24.77,44.22) ; U16.38 v1(24.77,39.85) ; v1(24.77,41.17) 30.1,41.17 31.75,39.52 U16.27
  BOTTOM w0.127: v1(24.77,39.85) v1(24.77,41.17) v1(24.77,44.22) ; v1(14.58,45.85) 13.33,47.1 7.2,47.1 6.57,47.73 6.57,63.99 7.46,64.88 7.98,64.88 9,65.89 9,82.44 J3.27
D<2>: length 80.4
  TOP w0.127: U16.40 v1(23.5,39.7) ; U16.29 v1(30.48,39.7)
  BOTTOM w0.127: 23.5,39.13 20.89,36.53 20.89,35.07 20,34.18 6.86,34.18 5.59,35.45 5.59,70.59 7.49,72.5 8.04,72.5 8.67,73.13 8.67,80.23 J3.26 ; 23.5,39.13 v1(23.5,39.7) ; 23.5,39.13 29.91,39.13 v1(30.48,39.7)
D<3>: length 79.4
  TOP w0.127: U16.30 v1(29.84,34.95) ; U16.41 22.86,36.49 22.94,36.41 v1(22.94,34.95)
  BOTTOM w0.127: J3.25 4.93,76.05 4.93,33.67 6.97,31.64 15.71,31.64 17.02,32.95 20.94,32.95 v1(22.94,34.95) v1(29.84,34.95)
D<4>: length 74.3
  TOP w0.127: v1(21.51,36.25) 21.59,36.32 U16.43 ; U16.32 28.57,36.55 28.27,36.25 v1(28.12,36.25)
  BOTTOM w0.127: J3.24 5.26,73.84 5.26,33.87 7.17,31.97 14.24,31.97 15.88,33.6 19.99,33.6 21.51,35.13 v1(21.51,36.25) 22.41,37.14 27.86,37.14 28.12,36.89 v1(28.12,36.25)
D<5>: length 64.1
  TOP w0.127: U16.44 v1(20.95,39.7) ; J3.23 6.57,72.61 6.57,45.18 7.08,44.67 20.36,44.67 v1(20.95,45.26) ; U16.33 v1(27.94,39.7)
  BOTTOM w0.127: v1(27.94,39.7) 27.94,43.1 25.78,45.26 v1(20.95,45.26) v1(20.95,39.7)
D<6>: length 65
  TOP w0.127: U16.35 26.67,34.74 25.4,33.47 20.99,33.47 v1(19.68,34.77) U16.46
  BOTTOM w0.127: J3.22 5.91,69.41 5.91,35.65 7.06,34.51 18.85,34.51 19.12,34.77 v1(19.68,34.77)
D<7>: length 58.4
  TOP w0.127: U16.36 26.04,39.53 25.15,40.42 19.2,40.42 19.05,40.27 ; v1(17.04,36.93) 17.04,39.25 18.06,40.27 19.05,40.27 ; U16.47 19.05,40.27
  BOTTOM w0.127: v1(17.04,36.93) 7.26,36.93 6.24,37.95 6.24,67.2 J3.21
D<8>: length 96.1
  TOP w0.127: U15.36 26.04,91.35 24.89,92.49 7.13,92.49 1.54,86.9 1.54,26.54 2.68,25.4 J3.4
D<9>: length 89.7
  TOP w0.127: U15.35 26.67,91.29 25.15,92.82 14.88,92.82 v1(14.63,93.07)
  BOTTOM w0.127: J3.5 4.28,31.28 4.28,89.64 7.45,92.82 14.63,92.82 14.63,93.06 v1(14.63,93.07)
D<10>: length 83.7
  TOP w0.127: U15.33 27.94,87.82 25.91,85.79 15.35,85.79 13.41,87.74 7.02,87.74 4.61,85.32 4.61,33.49 J3.6
D<11>: length 80.9
  TOP w0.127: J3.7 5.26,35.38 5.26,85.51 7.17,87.41 13.22,87.41 15.17,85.46 26.16,85.46 28.57,87.88 U15.32
D<12>: length 76.9
  TOP w0.127: U15.30 29.84,86.73 28.19,85.08 7.37,85.08 5.59,83.3 5.59,37.59 J3.8
D<13>: length 71.8
  TOP w0.127: U15.29 30.48,86.77 28.45,84.74 18.21,84.74 13.59,80.12 7.5,80.12 5.91,78.53 5.91,39.8 J3.9
D<14>: length 68.4
  TOP w0.127: J3.10 6.24,42.02 6.24,76.44 7.38,77.58 13.03,77.58 19.81,84.36 28.7,84.36 31.75,87.41 U15.27
D<15>: length 111.1
  TOP w0.127: v1(24.08,95.61) 24.08,95.6 27.69,95.6 32.39,90.9 U15.26 ; J3.11 9,41.8 9,30.32 8.11,29.43 7.13,29.43 3.95,32.6 3.95,86.72 7.51,90.28 13.95,90.28 15.52,91.85 v1(19.63,91.85)
  BOTTOM w0.127: v1(19.63,91.85) 19.63,94.08 21.16,95.6 24.08,95.6 v1(24.08,95.61)
DATA: length 57.8
  TOP w0.127: U7.14 v1(63.5,101.78)
  BOTTOM w0.127: v1(63.5,101.78) 61.49,103.79 19.02,103.79 17.36,102.14 17.36,95.03 U18.1
DCLK: length 56.5
  TOP w0.127: U18.2 27.38,100.41 36.7,100.41 v1(36.7,100.41) ; U7.10 v1(70.33,97.16)
  BOTTOM w0.127: v1(36.7,100.41) 68.18,100.41 70.34,98.25 70.34,97.16 v1(70.33,97.16)
DDIR: length 81.5
  TOP w0.127: v1(48.31,57.33) 48.05,57.59 35.61,57.59 33.02,54.99 U14.24 33.02,52.42 31.62,51.03 19.68,51.03 18.41,52.29 ; U14.1 18.41,52.29 ; 18.41,52.29 12.16,52.29 11.65,52.8 11.65,61.5 12.16,62.01 14.43,62.01 17.48,65.06 17.48,75.27 18.41,76.21 U15.1
  BOTTOM w0.127: v1(48.31,57.33) 48.61,57.33 48.89,57.33 48.89,63.5
DEN: length 72.5
  TOP w0.127: v1(16.61,90.91) 17.93,90.91 18.41,90.42 U15.48 ; 18.41,68.23 v1(18.41,70.21) ; 18.41,68.23 U14.48 ; 18.41,68.23 32.42,68.23 35.78,64.88 44.98,64.88 46.36,63.5
  BOTTOM w0.127: v1(18.41,70.21) 18.28,70.07 12.25,70.07 10.34,71.97 10.34,88.63 11.99,90.28 15.98,90.28 v1(16.61,90.91)
DHEN: length 12.6
  TOP w0.127: 43.81,63.5 42.76,64.55 34.95,64.55 34.64,64.86 33.49,64.86 33.02,64.39 U14.25
FPGA: length 45.8
  TOP w0.127: U7.30 v1(43.18,90.09)
  BOTTOM w0.127: U17.18 53.97,66.54 51.41,69.1 51.41,75.87 48.49,78.79 42.28,78.79 42.03,79.05 42.03,88.94 v1(43.18,90.09)
GAIN: length 168.1
  TOP w0.127: U2_1.6 113.8,31.14 113.89,31.24 v1(114.63,31.24) ; v1(113.61,99.29) 87.91,99.29 87.49,98.87 82.38,98.87 82.01,99.25 74.56,99.25 70.27,103.54 48.29,103.54 45.72,100.96 U7.28 ; U2_2.6 114.68,10.45 115.3,11.07 115.3,12.08 114.98,12.4 113.03,12.4 112.7,12.74 112.7,13.58 113.8,14.68 v1(114.7,14.68)
  BOTTOM w0.127: v1(113.61,99.29) 113.61,32.26 v1(114.63,31.24) 114.63,25.94 114.53,25.84 114.11,25.84 114.01,25.74 114.01,14.78 114.11,14.68 v1(114.7,14.68)
HS: length 41.9
  TOP w0.127: U7.29 v1(44.45,78.21)
  BOTTOM w0.127: v1(44.45,78.21) 44.45,67.72 44.7,67.47 48.63,67.47 51.44,64.67 U17.19
IO<0>: length 97.7
  TOP w0.127: v1(177.4,91.08) 181.05,91.08 181.08,91.05 182.24,91.05 U26.37 ; v1(170.4,79.08) 167.4,79.08 165.4,81.08 165.4,83.08 161.95,86.53 R20.2 ; v1(172.4,55.08) 182.27,55.08 U27.37
  BOTTOM w0.127: v1(172.4,55.08) 170.4,55.08 167.4,58.08 167.4,76.08 v1(170.4,79.08) 170.4,81.68 170.27,81.81 169.15,81.81 169.02,81.94 169.02,82.21 169.15,82.34 170.27,82.34 170.4,82.46 170.4,82.74 170.27,82.86 169.15,82.86 169.02,82.99 169.02,83.27 169.15,83.39 170.27,83.39 170.4,83.52 170.4,83.79 170.27,83.92 169.15,83.92 169.02,84.05 169.02,84.32 169.15,84.45 170.27,84.45 170.4,84.57 170.4,87.08 171.59,88.27 171.59,88.45 170.58,89.46 170.58,89.63 170.78,89.83 170.95,89.83 171.96,88.82 172.14,88.82 172.34,89.02 172.34,89.19 171.33,90.2 171.33,90.38 171.52,90.57 171.7,90.57 172.71,89.57 172.89,89.57 173.08,89.76 173.08,89.94 172.07,90.95 172.07,91.13 172.27,91.32 172.45,91.32 173.45,90.31 173.63,90.31 174.4,91.08 v1(177.4,91.08)
IO<1>: length 84.9
  TOP w0.127: v1(174.4,77.08) 165.4,77.08 157.98,84.5 R21.2 ; v1(178.4,90.25) U26.38 ; v1(176.4,54.31) U27.38
  BOTTOM w0.127: v1(176.4,54.31) 175.4,55.31 175.4,58.08 171.4,62.08 171.4,73.08 174.4,76.08 v1(174.4,77.08) 174.4,78.03 174.27,78.15 173.88,78.15 173.75,78.28 173.75,78.55 173.88,78.68 174.27,78.68 174.4,78.81 174.4,79.08 174.27,79.21 173.88,79.21 173.75,79.33 173.75,79.61 173.88,79.73 174.27,79.73 174.4,79.86 174.4,80.78 174.27,80.9 173.94,80.9 173.82,81.03 173.82,81.3 173.94,81.43 174.27,81.43 174.4,81.56 174.4,81.83 174.27,81.96 173.94,81.96 173.82,82.08 173.82,82.36 173.94,82.48 174.27,82.48 174.4,82.61 174.4,82.88 174.27,83.01 173.94,83.01 173.82,83.14 173.82,83.41 173.94,83.54 174.27,83.54 174.4,83.67 174.4,84.08 175.3,84.98 175.3,85.16 174.91,85.55 174.91,85.73 175.11,85.93 175.29,85.93 176.25,84.97 176.42,84.97 176.62,85.16 176.62,85.34 175.66,86.3 175.66,86.48 175.85,86.67 176.03,86.67 176.99,85.71 177.17,85.71 177.37,85.91 177.37,86.09 176.97,86.48 176.97,86.66 177.4,87.08 177.4,89.25 v1(178.4,90.25)
IO<2>: length 84.2
  TOP w0.127: R22.2 156.01,82.47 163.4,75.08 v1(169.4,75.08) ; U26.40 182.3,89.08 v1(176.4,89.08) ; v1(174.4,53.04) U27.40
  BOTTOM w0.127: v1(174.4,53.04) 172.97,54.47 172.97,55.32 172.64,55.65 171.79,55.65 171.4,56.04 171.4,56.08 168.4,59.08 168.4,74.08 v1(169.4,75.08) 170.12,75.8 170.12,75.98 169.23,76.87 169.23,77.04 169.42,77.24 169.6,77.24 170.49,76.35 170.67,76.35 171.4,77.08 171.4,78.33 171.53,78.45 171.81,78.45 171.94,78.58 171.94,78.85 171.81,78.98 171.53,78.98 171.4,79.11 171.4,79.38 171.53,79.51 171.81,79.51 171.94,79.64 171.94,79.91 171.81,80.04 171.53,80.04 171.4,80.16 171.4,80.44 171.53,80.56 171.81,80.56 171.94,80.69 171.94,80.96 171.81,81.09 171.53,81.09 171.4,81.22 171.4,82.27 171.27,82.4 170.89,82.4 170.77,82.52 170.77,82.8 170.89,82.92 171.27,82.92 171.4,83.05 171.4,83.32 171.27,83.45 170.89,83.45 170.77,83.58 170.77,83.85 170.89,83.98 171.27,83.98 171.4,84.1 171.4,84.38 171.27,84.5 170.89,84.5 170.77,84.63 170.77,84.91 170.89,85.03 171.27,85.03 171.4,85.16 171.4,86.08 174.4,89.08 v1(176.4,89.08)
IO<3>: length 80.7
  TOP w0.127: v1(173.4,73.08) 163.4,73.08 156.04,80.44 R23.2 ; U27.41 182.24,52.23 181.08,52.23 180.92,52.08 v1(177.4,52.08) ; U26.41 182.24,88.17 181.08,88.17 180.98,88.08 v1(178.4,88.08)
  BOTTOM w0.127: v1(177.4,52.08) 177.4,56.08 176.07,57.41 176.07,59.41 172.4,63.08 172.4,71.08 173.4,72.08 v1(173.4,73.08) 175.4,75.08 175.4,77.96 175.27,78.08 174.92,78.08 174.8,78.21 174.8,78.48 174.92,78.61 175.88,78.61 176,78.74 176,79.01 175.88,79.14 174.92,79.14 174.8,79.26 174.8,79.54 174.92,79.66 175.88,79.66 176,79.79 176,80.06 175.88,80.19 174.92,80.19 174.8,80.32 174.8,80.59 174.92,80.72 175.88,80.72 176,80.84 176,81.12 175.88,81.24 174.92,81.24 174.8,81.37 174.8,81.64 174.92,81.77 175.88,81.77 176,81.9 176,82.17 175.88,82.3 175.53,82.3 175.4,82.43 175.4,83.08 178.4,86.08 v1(178.4,88.08)
IO<4>: length 78.2
  TOP w0.127: v1(169.4,71.08) 163.4,71.08 156.08,78.4 R24.2 ; v1(175.4,87.08) 182.4,87.08 U26.43 ; U27.43 182.35,51.08 v1(175.4,51.08)
  BOTTOM w0.127: v1(175.4,87.08) 174.4,87.08 172.4,85.08 172.4,84.65 172.53,84.53 172.92,84.53 173.04,84.4 173.04,84.13 172.92,84 172.53,84 172.4,83.87 172.4,83.6 172.53,83.47 172.92,83.47 173.04,83.35 173.04,83.07 172.92,82.95 172.53,82.95 172.4,82.82 172.4,82.55 172.53,82.42 172.92,82.42 173.04,82.29 173.04,82.02 172.92,81.89 172.53,81.89 172.4,81.77 172.4,81.49 172.53,81.36 172.92,81.36 173.04,81.24 173.04,80.96 172.92,80.84 172.53,80.84 172.4,80.71 172.4,77.08 169.4,74.08 v1(169.4,71.08) 169.4,61.08 173.4,57.08 173.4,55.08 175.4,53.08 v1(175.4,51.08)
IO<5>: length 72.4
  TOP w0.127: U27.44 182.24,50.33 181.08,50.33 180.83,50.08 v1(179.4,50.08) ; v1(174.4,69.08) 163.4,69.08 156.11,76.37 R25.2 ; v1(179.4,86.08) 180.89,86.08 181.08,86.27 182.24,86.27 U26.44
  BOTTOM w0.127: v1(179.4,50.08) 179.4,56.08 177.4,58.08 177.4,64.08 174.4,67.08 v1(174.4,69.08) 178.4,73.08 178.4,78.81 178.27,78.94 178.14,78.94 178.01,79.07 178.01,79.34 178.14,79.47 178.66,79.47 178.79,79.6 178.79,79.87 178.66,80 178.14,80 178.01,80.12 178.01,80.4 178.14,80.52 178.66,80.52 178.79,80.65 178.79,80.92 178.66,81.05 178.53,81.05 178.4,81.18 178.4,85.08 v1(179.4,86.08)
IO<6>: length 73.8
  TOP w0.127: v1(176.4,49.08) 182.26,49.08 U27.46 ; v1(174.4,85.08) 182.32,85.08 U26.46 ; v1(170.4,67.08) 163.4,67.08 156.14,74.34 R26.2
  BOTTOM w0.127: v1(174.4,85.08) 173.4,84.08 173.4,77.08 170.4,74.08 v1(170.4,67.08) 170.4,62.08 174.4,58.08 174.4,55.08 176.4,53.08 v1(176.4,49.08)
IO<7>: length 74.6
  TOP w0.127: v1(173.4,65.08) 161.4,65.08 154.17,72.31 R27.2 ; U26.47 182.24,84.36 181.08,84.36 180.79,84.08 v1(177.4,84.08) ; U27.47 182.24,48.42 181.08,48.42 180.73,48.08 v1(179.4,48.08)
  BOTTOM w0.127: v1(179.4,48.08) 178.4,49.08 178.4,56.08 176.4,58.08 176.4,61.08 175.08,62.4 174.91,62.4 174.38,61.87 174.2,61.87 174.01,62.07 174.01,62.25 175.23,63.47 175.23,63.65 175.04,63.84 174.86,63.84 174.34,63.32 174.16,63.32 173.4,64.08 v1(173.4,65.08) 173.4,70.08 177.4,74.08 v1(177.4,84.08)
IOA<0>: length 72.4
  TOP w0.127: U26.2 193.49,84.53 194.82,85.86 195.32,85.86 208.9,72.28 214.3,72.28 220.9,65.68 241.9,65.68 246.2,69.98 249.93,69.98 J5.45
IOA<1>: length 77.7
  TOP w0.127: J5.13 256.21,68.78 251.9,68.78 250.17,70.51 245.98,70.51 241.68,66.21 221.12,66.21 214.52,72.81 209.12,72.81 195.54,86.39 194.6,86.39 193.38,85.17 U26.3
IOA<2>: length 71.4
  TOP w0.127: U26.5 193.49,86.44 193.97,86.92 195.75,86.92 209.34,73.33 214.74,73.33 221.34,66.73 241.46,66.73 245.76,71.03 251.42,71.03 252.48,69.98
IOA<3>: length 76.8
  TOP w0.127: U26.6 193.38,87.07 193.75,87.44 195.97,87.44 209.56,73.86 214.96,73.86 221.56,67.26 241.24,67.26 245.54,71.56 251.94,71.56 252.04,71.47 252.91,71.47 253.01,71.56 255.97,71.56 257.56,69.98
IOA<4>: length 71.1
  TOP w0.127: U26.8 193.38,88.34 193.75,87.97 196.19,87.97 209.78,74.39 215.18,74.39 221.78,67.79 241.02,67.79 245.32,72.09 252.05,72.09 J5.43
IOA<5>: length 77.1
  TOP w0.127: U26.9 193.49,88.98 193.97,88.5 196.41,88.5 209.99,74.91 215.39,74.91 221.99,68.31 240.8,68.31 245.1,72.61 250.44,72.61 251.6,73.78 256.29,73.78 J5.11
IOA<6>: length 72.4
  TOP w0.127: U26.11 193.38,90.25 194.6,89.02 196.63,89.02 210.21,75.44 215.61,75.44 222.21,68.84 240.59,68.84 244.89,73.14 249.47,73.14 249.6,73.27 249.6,73.68 250.3,74.38 251.8,74.38 J5.42
IOA<7>: length 78.8
  TOP w0.127: J5.10 256.5,76.11 250.03,76.11 249.27,75.35 249.27,73.8 249.15,73.67 244.67,73.67 240.37,69.37 222.43,69.37 215.83,75.97 210.43,75.97 196.85,89.55 194.82,89.55 193.49,90.88 U26.12
IOB<0>: length 71.1
  TOP w0.127: J5.55 249.57,42.04 249.44,41.91 249.44,41.41 249.32,41.28 249.04,41.28 248.92,41.41 248.92,41.91 248.79,42.04 248.52,42.04 248.39,41.91 248.39,41.41 248.26,41.28 247.99,41.28 247.86,41.41 247.86,41.91 247.73,42.04 247.46,42.04 247.33,41.91 247.33,41.41 247.21,41.28 246.94,41.28 246.81,41.41 246.81,41.91 246.68,42.04 246.41,42.04 246.28,41.91 246.28,41.41 246.15,41.28 245.88,41.28 245.75,41.41 245.75,41.91 245.63,42.04 243.84,42.04 233.8,52.08 214.5,52.08 211.64,49.22 194.48,49.22 193.85,48.59 U27.2
IOB<1>: length 71.7
  TOP w0.127: J5.23 256.07,43.53 244.66,43.53 242.69,45.5 235.37,52.81 214.2,52.81 211.34,49.95 194.22,49.95 193.49,49.23 U27.3
IOB<2>: length 71.2
  TOP w0.127: J5.54 250.5,44.58 250.37,44.7 250.37,45.25 250.24,45.38 249.97,45.38 249.84,45.25 249.84,44.7 249.72,44.58 249.44,44.58 249.32,44.7 249.32,45.25 249.19,45.38 248.92,45.38 248.79,45.25 248.79,44.7 248.66,44.58 245.8,44.58 245.04,45.34 245.04,45.51 245.32,45.78 245.32,45.96 245.12,46.16 244.94,46.16 244.67,45.89 244.49,45.89 244.3,46.08 244.3,46.26 244.57,46.53 244.57,46.71 244.38,46.9 244.2,46.9 243.93,46.63 243.75,46.63 243.55,46.83 243.55,47.01 243.82,47.28 243.82,47.45 243.63,47.65 243.45,47.65 243.18,47.38 243,47.38 236.84,53.53 213.9,53.53 211.04,50.68 193.91,50.68 193.73,50.5 U27.5
IOB<3>: length 73.3
  TOP w0.127: U27.6 193.38,51.13 193.65,51.4 210.74,51.4 213.59,54.26 238.02,54.26 239.53,52.75 239.53,52.57 239.41,52.45 239.41,52.27 239.6,52.08 239.78,52.08 239.9,52.2 240.08,52.2 240.27,52.01 240.27,51.83 240.15,51.71 240.15,51.53 240.35,51.33 240.52,51.33 240.65,51.45 240.82,51.45 241.02,51.26 241.02,51.08 240.9,50.96 240.9,50.78 241.09,50.59 241.27,50.59 241.39,50.71 241.57,50.71 241.77,50.51 241.77,50.34 241.64,50.21 241.64,50.04 241.84,49.84 242.02,49.84 242.14,49.96 242.32,49.96 245.77,46.53 246.3,46 256.14,46 J5.22
IOB<4>: length 69.8
  TOP w0.127: 252.48,47.12 252.4,47.04 246.96,47.04 245.81,48.19 245.63,48.19 245.3,47.86 245.12,47.86 244.93,48.05 244.93,48.23 245.26,48.56 245.26,48.74 245.06,48.93 244.88,48.93 244.56,48.6 244.38,48.6 244.18,48.8 244.18,48.98 244.51,49.31 244.51,49.48 244.32,49.68 244.14,49.68 243.81,49.35 243.63,49.35 243.44,49.55 243.44,49.72 243.77,50.05 243.77,50.23 242.27,51.73 242.27,51.91 242.58,52.22 242.58,52.4 242.39,52.59 242.21,52.59 241.9,52.28 241.72,52.28 239.01,54.99 213.29,54.99 210.43,52.13 193.65,52.13 193.38,52.4 U27.8
IOB<5>: length 72.5
  TOP w0.127: 257.56,47.12 256.5,48.17 252.04,48.17 251.43,47.55 248.13,47.55 244.52,51.16 244.52,51.34 244.69,51.51 244.69,51.69 244.5,51.88 244.32,51.88 244.15,51.71 243.97,51.71 243.77,51.91 243.77,52.08 243.94,52.26 243.94,52.43 243.75,52.63 243.57,52.63 243.4,52.46 243.22,52.46 239.96,55.72 212.99,55.72 210.13,52.86 193.91,52.86 193.73,53.04 U27.9
IOB<6>: length 71.8
  TOP w0.127: 252.48,49.66 250.89,48.07 249.01,48.07 247.47,49.61 247.3,49.61 247.01,49.32 246.83,49.32 246.64,49.51 246.64,49.69 247.39,50.44 247.39,50.62 247.19,50.82 247.01,50.82 246.73,50.53 246.55,50.53 243.57,53.51 243.57,53.69 243.86,53.98 243.86,54.16 243.66,54.35 243.48,54.35 242.73,53.6 242.55,53.6 242.35,53.79 242.35,53.97 243.11,54.73 243.11,54.9 242.92,55.1 242.74,55.1 242.45,54.81 242.27,54.81 240.64,56.44 212.69,56.44 209.83,53.58 194.22,53.58 193.49,54.31 U27.11
IOB<7>: length 157.4
  TOP w0.127: 257.56,49.66 256.48,48.59 255.03,48.59 252.91,50.71 252.04,50.71 251.42,50.09 251.42,49.22 250.79,48.59 250,48.59 241.41,57.17 216.7,57.17 216.6,57.27 216.6,58.08 216.5,58.18 196.5,58.18 196.4,58.08 196.4,57.38 196.5,57.28 209.43,57.28 209.53,57.18 209.53,54.41 209.43,54.31 208.64,54.31 208.64,56.78 208.13,56.78 208.13,54.31 207.62,54.31 207.62,56.78 207.11,56.78 207.11,54.31 206.61,54.31 206.61,56.78 206.1,56.78 206.1,54.31 205.59,54.31 205.59,56.78 205.08,56.78 205.08,54.31 204.57,54.31 204.57,56.78 204.07,56.78 204.07,54.31 203.56,54.31 203.56,56.78 203.05,56.78 203.05,54.31 202.54,54.31 202.54,56.78 202.03,56.78 202.03,54.31 201.53,54.31 201.53,56.78 201.02,56.78 201.02,54.31 200.51,54.31 200.51,56.78 200,56.78 200,54.31 199.49,54.31 199.49,56.78 198.99,56.78 198.99,54.31 198.48,54.31 198.48,56.78 197.97,56.78 197.97,54.31 194.48,54.31 193.85,54.94 U27.12
MCLK: length 131.9
  TOP w0.127: v1(28.9,68.78) 35.27,75.14 35.27,95.26 37.68,97.67 40.04,97.67 41.91,99.54 U7.31 ; J3.52 14.27,66.04 v1(14.58,65.73) ; v1(72.9,60.53) 72.9,60.53 v1(29.11,60.53)
  BOTTOM w0.127: U22.2 82.12,51.31 v1(72.9,60.53) ; 28.69,62.97 28.69,60.53 v1(29.11,60.53) ; 28.69,62.97 13.94,62.97 13.47,62.5 12.21,62.5 11.7,63.01 11.7,63.97 12.33,64.6 13.45,64.6 v1(14.58,65.73) ; 28.69,62.97 28.81,63.09 28.81,68.69 v1(28.9,68.78)
MRD: length 56.4
  TOP w0.127: v1(14.73,56.03) 14.73,57.8 15.49,58.57 42.86,58.57 43.7,59.41 59.05,59.41 v1(59.05,59.41)
  BOTTOM w0.127: v1(14.73,56.03) 14.73,52.83 J3.46 ; U17.9 v1(59.05,59.41)
MWR: length 57.6
  TOP w0.127: 61.59,55.88 60.22,54.5 53.83,54.5 52.81,55.52 52.81,56.46 52.02,57.26 51.29,57.26 50.27,56.24 50.27,55.72 49.38,54.83 48.37,54.83 47.73,55.46 47.73,56.04 46.84,56.93 37.73,56.93 35.45,54.65 35.45,54.38 29.1,48.03 13.98,48.03 13.75,48.26 J3.45
NCS: length 47.6
  TOP w0.127: U7.11 v1(69.39,98.42)
  BOTTOM w0.127: U18.4 31.33,99.27 57.53,99.27 58.65,98.16 68.56,98.16 68.82,98.42 v1(69.39,98.42)
OE: length 238.5
  TOP w0.127: v1(138.56,58.04) 139.13,58.04 139.37,57.8 U8.1 141.53,57.8 146.35,52.98 146.35,39.67 157.01,29 188.02,29 189.8,27.22 189.8,27.1 193.1,23.79 U25.1 ; 40.64,101.53 39.35,101.53 37.22,99.41 27.05,99.41 23.5,95.85 U18.3 ; 40.64,101.53 43.96,104.85 116,104.85 119.1,101.75 119.1,94.99 128.95,85.13 U24.1 138.55,85.13 v1(138.56,85.14) ; 40.64,101.53 U7.32
  BOTTOM w0.127: v1(138.56,58.04) v1(138.56,85.14)
OUTA: length 22.1
  TOP w0.8: U3_1.6 95.6,25.88 95.6,24.28 96.04,23.84 113.7,23.84 114.62,24.77 L1.1
OUTB: length 22.1
  BOTTOM w0.8: L4.1 111.94,2.09 108.16,2.09 108.15,2.08 97.2,2.08 95.9,3.38 95.9,5.18 96.3,5.58
Q0: length 30.3
  TOP w0.127: U19.12 52.96,51.03 54.98,49 75.95,49 79.12,45.83 R9.2
Q1: length 4.8
  TOP w0.127: R9.1 82.44,44.58 82.7,44.83 82.7,46.21 CR4.1
Q2: length 26.1
  TOP w0.127: R8.2 72.39,45.5 69.22,48.68 52.77,48.68 50.42,51.03 50.42,51.74
Q3: length 5.1
  TOP w0.127: CR3.1 75.97,45.96 75.97,44.58 75.71,44.32 R8.1
Q4: length 21.5
  TOP w0.127: R7.2 65.79,44.26 63.71,46.33 52.57,46.33 47.88,51.03 47.88,51.74
Q5: length 4.5
  TOP w0.127: CR2.1 69.36,46.21 69.36,45.55 68.07,44.26 R7.1
Q6: length 18.1
  TOP w0.127: 45.34,51.74 45.34,51.03 50.69,45.68 58.4,45.68 59.82,44.26 R6.2
Q7: length 5.6
  TOP w0.127: R6.1 v1(63.47,44.2)
  BOTTOM w0.127: CR1.1 61.59,46.08 v1(63.47,44.2)
RA<0>: length 192
  TOP w0.127: U4.5 80.64,102.36 80.77,102.49 v1(81.35,102.49) ; 104.14,89.15 v1(96.37,89.15) ; 104.14,89.15 v1(105.89,89.15) ; 104.14,89.15 U102.5 ; U2.5 v1(80.64,86.11) v1(82.47,86.11) ; U3.5 v1(104.14,63.12) ; v1(53.09,61.44) 53.46,61.07 73.43,61.07 74.52,59.99 79.75,59.99 80.64,60.88 U5.5 v1(80.64,63.12) ; U6.5 104.14,102.18 104.45,102.49 v1(104.72,102.49) ; U7.58 v1(45.72,68.94) ; v1(104.83,76.43) 104.14,75.74 U101.5 ; U1.5 v1(80.64,75.82)
  BOTTOM w0.127: v1(53.09,61.44) 53.09,62.01 52.81,62.29 52.81,65.83 49.71,68.93 45.72,68.93 v1(45.72,68.94) ; v1(104.14,63.12) 104.83,63.8 v1(104.83,76.43) 105.98,77.58 105.98,89.07 v1(105.89,89.15) 104.73,90.32 v1(104.73,102.49) ; v1(80.64,86.11) 80.64,84.13 80.08,83.56 80.08,80.92 80.64,80.35 v1(80.64,75.82) 80.64,73.82 80.08,73.26 80.08,63.69 v1(80.64,63.12) ; v1(96.37,89.15) 96.37,106.87 93.7,109.53 81.6,109.53 81.35,109.28 v1(81.35,102.49) 81.35,94.55 82.48,93.41 82.48,86.12 v1(82.47,86.11)
